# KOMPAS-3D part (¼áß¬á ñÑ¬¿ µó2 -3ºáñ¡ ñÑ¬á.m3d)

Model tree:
1. Эскиз:1
2. Операция выдавливания:1
     Толщина стенки 1 = 7; Толщина стенки 2 = 6; Расстояние 1 = 0.6
3. Эскиз:2
4. Вырезать элемент выдавливания:1
     Толщина стенки 2 = 15; Расстояние 1 = 10
5. Эскиз:3
6. Вырезать элемент выдавливания:2
     Толщина стенки 1 = 8; Толщина стенки 2 = 15; Расстояние 1 = 10
7. Эскиз:4
8. Вырезать элемент выдавливания:3
     Толщина стенки 1 = 7; Расстояние 1 = 10
9. Эскиз:6
10. Вырезать элемент выдавливания:5
     Толщина стенки 1 = 7; Расстояние 1 = 10
11. Эскиз:7
12. Операция выдавливания:2
     Толщина стенки 1 = 7; Толщина стенки 2 = 6; Расстояние 1 = 0.6; Расстояние 2 = 0.6
